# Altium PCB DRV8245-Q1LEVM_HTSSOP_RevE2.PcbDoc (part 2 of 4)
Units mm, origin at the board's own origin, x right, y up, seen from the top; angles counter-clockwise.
Board outline 81.9 x 103.6 mm, 4 copper layers (Top Layer, Signal Layer 1, Signal Layer 2, Bottom Layer), stack 1.554 mm thick; 187 components, 116 nets, 590 pads, 1182 vias.
Unrouted connection lines stored in the file: 116.
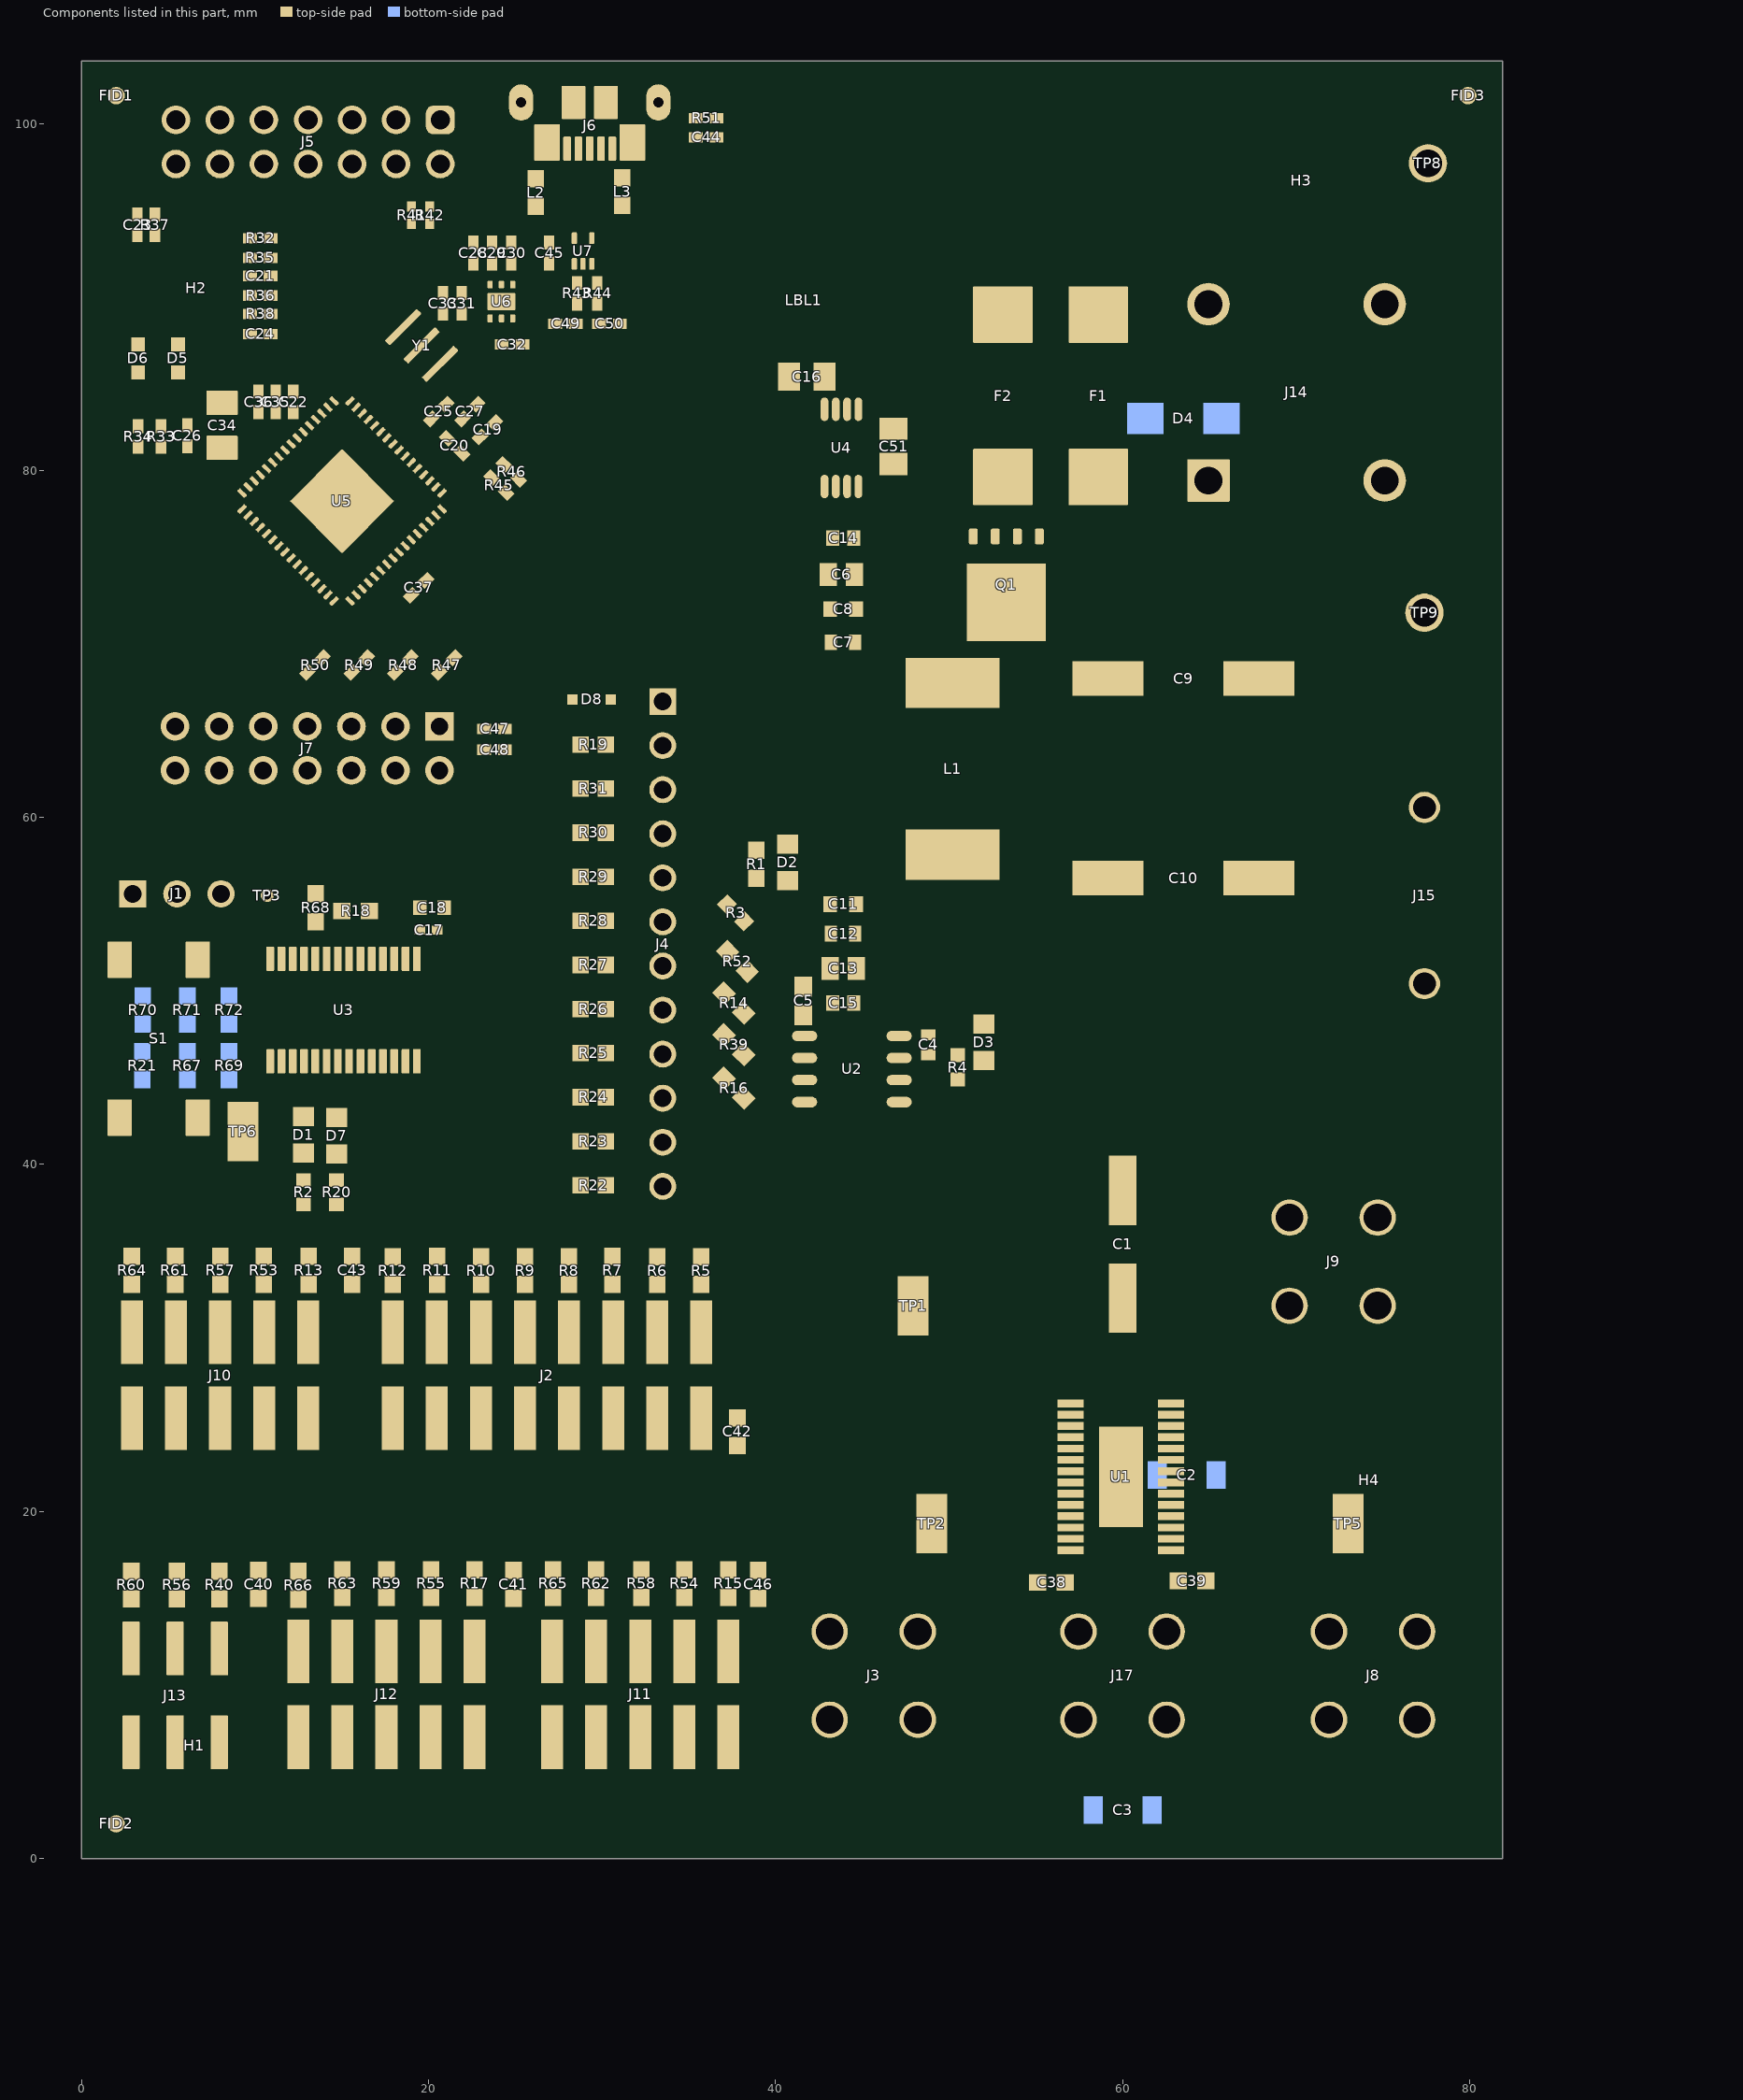
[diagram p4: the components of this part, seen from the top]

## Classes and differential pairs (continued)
component class AssemblyNote: ZZ1 ZZ2 ZZ3 ZZ4
component class Label: LBL1
differential pair USB_D: +USB_D_P -USB_D_N
differential pair EZFET_D: +EZFET_D_P -EZFET_D_N

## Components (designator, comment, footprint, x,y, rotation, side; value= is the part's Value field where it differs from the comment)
C1 "EEE-2AA100UP" SM_RADIAL_E 60,35.4 r270 top value=10uF
C2 "C3216X7R2A104K160AA" 1206_180 63.7,22.1 r180 bottom value=0.1uF
C3 "C3216X7R2A104K160AA" 1206_180 60,2.8 r0 bottom value=0.1uF
C4 "CL10B104JB8NNNC" FP-CL10-0_1-MFG 48.8,46.9 r270 top value=0.1uF
C5 "CL10A226MQ8NUNE" FP-CL10-IPC_A 41.6,49.427 r90 top
C6 "1uF" CAPC2013X135X45LL10T25 43.8,74 r0 top
C7 "0.1uF" CAPC0603(1608)100_L 43.9,70.1 r0 top value=100nF
C8 "CC0603KPX7R9BB103" FP-CC0603-DA-MFG 43.9,72 r0 top value="10 nF"
C9 "EEE-FK1H151P" SM_RADIAL_G 63.5,68 r0 top value=150uF
C10 "EEE-FK1H151P" SM_RADIAL_G 63.5,56.5 r0 top value=150uF
C11 "CC0603KPX7R9BB103" FP-CC0603-DA-MFG 43.9,55 r180 top value="10 nF"
C12 "0.1uF" CAPC0603(1608)100_L 43.9,53.3 r0 top value=100nF
C13 "1uF" CAPC2013X135X45LL10T25 43.9,51.3 r0 top
C14 "1nF" FP-C0603C-CF-MFG#1 44,76.1 r180 top value="1,000 pF"
C15 "1nF" FP-C0603C-CF-MFG#2 43.9,49.3 r180 top value="1,000 pF"
C16 "08055A101JAT2A" 0805_HV 41.8,85.4 r180 top value=100pF
C17 "Capacitor" 0402_065L 20,53.5 r0 top value=4.7uF
C18 "885012206020" 0603L 20.2,54.8 r0 top value=0.1uF
C19 "C1005X5R1A475M050BC" 0402 23.397,82.347 r45 top value=4.7uF
C20 "GRM155R61A104KA01D" 0402 21.501,81.429 r315 top value=0.1uF
C21 "C1005C0G1H330J050BA" 0402 10.302,91.208 r180 top value=33pF
C22 "GRM155R61A104KA01D" 0402 12.2,83.95 r90 top value=0.1uF
C23 "GRM155R71H102KA01D" 0402 3.228,94.149 r270 top value=1000pF
C24 "C1005C0G1H330J050BA" 0402 10.302,87.856 r180 top value=33pF
C25 "GRM155R61A224KE19D" 0402 20.583,83.39 r45 top value=0.22uF
C26 "GRM155R61C474KE01" 0402 6.1,82 r90 top value=0.47uF
C27 "GRM155R61A224KE19D" 0402 22.382,83.39 r45 top value=0.22uF
C28 "885012105012" 0402 22.577,92.525 r90 top value=1uF
C29 "GRM155R61A104KA01D" 0402 23.655,92.525 r90 top value=0.1uF
C30 "GRM155R71C103KA01D" 0402 24.774,92.525 r90 top value=0.01uF
C31 "2.2uF" 0402 21.905,89.625 r90 top
C32 "GRM155R71C103KA01D" 0402 24.814,87.256 r0 top value=0.01uF
C33 "885012105012" 0402 20.831,89.625 r90 top value=1uF
C34 "T520A106M010ATE080" 3216-18 8.1,82.6 r90 top value=10uF
C35 "GRM155R61A104KA01D" 0402 11.19,83.95 r90 top value=0.1uF
C36 "GRM155R61A104KA01D" 0402 10.205,83.95 r90 top value=0.1uF
C37 "GRM155R61A104KA01D" 0402 19.43,73.233 r225 top value=0.1uF
C38 "CGA3E2X7R2A102K080AA" 0603 55.9,15.9 r180 top value=1000pF
C39 "CGA3E2X7R2A102K080AA" 0603 64,16 r0 top value=1000pF
C40 "CGA3E2X7R2A102K080AA" 0603 10.2,15.8 r270 top value=1000pF
C41 "CGA3E2X7R2A102K080AA" 0603 24.9,15.8 r270 top value=1000pF
C42 "CGA3E2X7R2A102K080AA" 0603 37.8,24.6 r90 top value=1000pF
C43 "CGA3E2X7R2A102K080AA" 0603 15.6,33.9 r270 top value=1000pF
C44 "GRM155R61A224KE19D" 0402 36,99.2 r0 top value=0.22uF
C45 "GRM155R61A104KA01D" 0402 26.955,92.525 r90 top value=0.1uF
C46 "CGA3E2X7R2A102K080AA" 0603 39,15.8 r270 top value=1000pF
C47 "GRM1555C1H100FA01D" 0402 23.8,65.1 r180 top value=10pF
C48 "GRM1555C1H100FA01D" 0402 23.8,63.9 r180 top value=10pF
C49 "GRM1555C1H100FA01D" 0402 27.891,88.458 r180 top value=10pF
C50 "GRM1555C1H100FA01D" 0402 30.429,88.458 r0 top value=10pF
C51 "C2012X5R1H225K125AB" 0805_HV 46.8,81.384 r90 top value=2.2uF
D1 "150080VS75000" 0805_A 12.8,41.7 r90 top
D2 "150080SS75000" 0805_A 40.7,57.4 r90 top
D3 "150080VS75000" 0805_A 52,47.05 r90 top
D4 "SMAJ36CA" FP-SMAJ-CA-MFG 63.5,83 r180 bottom
D5 "150060RS75000" WL-SMCW_RED 5.561,86.456 r270 top value=Red
D6 "CMP-0002894-2" WL-SMCW_GREEN 3.258,86.456 r270 top value=Green
D7 "150080VS75000" 0805_A 14.7,41.65 r90 top
D8 "BAT165E6327HTSA1" SOD-323 29.4,66.8 r180 top value=40V
F1 "0463030.ER" Fuse_0463 58.6,84.3 r90 top
F2 "0463030.ER" Fuse_0463 53.1,84.3 r90 top
FID1 "Fiducial" Fiducial10-20 2,101.6 r0 top
FID2 "Fiducial" Fiducial10-20 2,2 r90 top
FID3 "Fiducial" Fiducial10-20 79.9,101.6 r0 top
H1 "SJ-5303 (CLEAR)" Bumpon_SJ5003Transparent 6.5,6.5 r0 bottom
H2 "SJ-5303 (CLEAR)" Bumpon_SJ5003Transparent 6.6,90.5 r0 bottom
H3 "SJ-5303 (CLEAR)" Bumpon_SJ5003Transparent 70.3,96.7 r0 bottom
H4 "SJ-5303 (CLEAR)" Bumpon_SJ5003Transparent 74.2,21.8 r180 bottom
J1 "PR20203VBNN" FP-PR20203VBNN-MFG 5.5,55.6 r0 top
J2 "TSM-108-01-L-DV" Samtec_TSM-108-01-x-DV 26.832,27.851 r270 top
J3 "CT3151SP-2" CTE_CT3151SP-2 45.66,-10.898 r90 top
J4 "PBC12SABN" Sullins_PxC12SABN 33.5,52.71 r270 top
J5 "61301421121" Wurth_61301421121 13.056,98.93 r270 top
J6 "CMP-0055311-1" Molex_1051640001 29.291,102.654 r180 top
J7 "PEC07DAAN" CONN_PEC07DAAN 13.015,63.978 r180 top
J8 "CT3151SP-2" CTE_CT3151SP-2 74.44,-10.898 r90 top
J9 "CT3151SP-2" CTE_CT3151SP-2 93.6,34.4 r180 top
J10 "TSM-105-01-L-DV-P" Samtec_TSM-105-01-x-DV 7.99,27.851 r270 top
J11 "TSM-105-01-L-DV-P" Samtec_TSM-105-01-x-DV 32.204,9.465 r270 top
J12 "TSM-105-01-L-DV-P" Samtec_TSM-105-01-x-DV 17.577,9.465 r270 top
J13 "61000621121" Wurth_61000621121 5.4,9.4 r270 top
J14 "691256610002" FP-691256610002_HDR2-MFG 72.5,84.5 r90 top
J15 "D3082-05" Harwin_D3082-05 77.4,55.5 r90 top
J17 "CT3151SP-0" CTE_CT3151SP-0 60,-10.898 r90 top
L1 "1uH" WE-HCC-1210 50.2,62.8 r270 top
L2 "BLM18AG151BH1D" 0603 26.174,96.01 r270 top value="150 ohm"
L3 "BLM18AG151BH1D" 0603 31.154,96.066 r270 top value="150 ohm"
LBL1 "THT-14-423-10" Label_650x200 41.6,89.8 r0 top
Logo1 "CE Mark" CE_Mark_5mm 33.6,84 r180 bottom
Logo2 "Texas Instruments" TI_Stacked_Overlay_Small 55.2,99 r0 top
Logo3 "FCC disclaimer" FCC_disclaimer -79.62,84.1 r270 bottom
Logo4 "WEEE logo" WEEE_Minimum 33.7,76.8 r180 bottom
Logo5 "CAUTION.  READ USER GUIDE BEFORE USE" IEC_Caution_Small 60.4,47.9 r0 top
LOGO6 "CAUTION HOT SURFACE" IEC_HotSurface_Small 52.2,26.1 r0 top
Q1 "CSD18513Q5A" DQJ0008A 53.3,73.4 r270 top value=40V
R1 "RC0603JR-0710KL" 0603 38.9,57.3 r90 top value=10k
R2 "CMP-0025785-4" 0603L 12.8,38.4 r90 top value=330
R3 "CMP-0025785-4" 0603L 37.7,54.5 r315 top value=330
R4 "CRCW06034K99FKEAC" 0603L 50.5,45.6 r270 top value=4.99k
R5 "RC0603FR-07470RL" 0603 35.722,33.882 r270 top value=470
R6 "RC0603FR-07680RL" 0603 33.182,33.882 r270 top value=680
R7 "RC0603FR-071KL" 0603 30.6,33.9 r270 top value=1.00k
R8 "RC0603FR-071K5L" 0603 28.102,33.882 r270 top value=1.50k
R9 "RC0603FR-072K2L" 0603 25.562,33.882 r270 top value=2.20k
R10 "RC0603FR-073K3L" 0603 23.022,33.882 r270 top value=3.30k
R11 "RC0603FR-074K7L" 0603 20.5,33.9 r270 top value=4.70k
R12 "RC0603FR-076K8L" 0603 17.942,33.882 r270 top value=6.80k
R13 "PMR03EZPJ000" 0603 13.1,33.9 r90 top value=0
R14 "PMR03EZPJ000" 0603 37.6,49.3 r135 top value=0
R15 "PMR03EZPJ000" 0603 37.284,15.846 r90 top value=0
R16 "PMR03EZPJ000" 0603 37.6,44.4 r135 top value=0
R17 "PMR03EZPJ000" 0603 22.657,15.846 r90 top value=0
R18 "RC0603JR-0747KL" 0603 15.8,54.6 r180 top value=47k
R19 "CRCW06030000Z0EAHP" RESC1609X55X30NL10T20 29.5,64.2 r0 top value=0
R20 "CMP-0025785-4" 0603L 14.7,38.4 r90 top value=330
R21 "RC0603JR-0710KL" 0603 3.5,45.7 r90 bottom value=10k
R22 "CRCW06030000Z0EAHP" RESC1609X55X30NL10T20 29.5,38.8 r0 top value=0
R23 "CRCW06030000Z0EAHP" RESC1609X55X30NL10T20 29.5,41.34 r0 top value=0
R24 "CRCW06030000Z0EAHP" RESC1609X55X30NL10T20 29.5,43.88 r0 top value=0
R25 "CRCW06030000Z0EAHP" RESC1609X55X30NL10T20 29.5,46.42 r0 top value=0
R26 "CRCW06030000Z0EAHP" RESC1609X55X30NL10T20 29.5,48.96 r0 top value=0
R27 "CRCW06030000Z0EAHP" RESC1609X55X30NL10T20 29.5,51.5 r0 top value=0
R28 "CRCW06030000Z0EAHP" RESC1609X55X30NL10T20 29.5,54.04 r0 top value=0
R29 "CRCW06030000Z0EAHP" RESC1609X55X30NL10T20 29.5,56.58 r0 top value=0
R30 "CRCW06030000Z0EAHP" RESC1609X55X30NL10T20 29.5,59.12 r0 top value=0
R31 "CRCW06030000Z0EAHP" RESC1609X55X30NL10T20 29.5,61.66 r0 top value=0
R32 "CRCW0402240KFKED" 0402 10.314,93.383 r180 top value=240k
R33 "CRCW0402470RJNED" 0402 4.578,81.956 r270 top value=470
R34 "CRCW0402390RJNED" 0402 3.258,81.956 r270 top value=390
R35 "CRCW0402150KFKED" 0402 10.302,92.252 r0 top value=150k
R36 "RC0402FR-07220KL" 0402 10.305,90.081 r180 top value=220k
R37 "CRCW040247K0JNED" 0402 4.228,94.149 r270 top value=47k
R38 "RC0402FR-07220KL" 0402 10.305,89.02 r0 top value=220k
R39 "PMR03EZPJ000" 0603 37.6,46.9 r135 top value=0
R40 "PMR03EZPJ000" 0603 7.95,15.761 r90 top value=0
R41 "ERJ-2GE0R00X" 0402L 19.011,94.708 r90 top value=0
R42 "ERJ-2GE0R00X" 0402L 20.062,94.708 r90 top value=0
R43 "CRCW040227R0JNED" 0402 28.559,90.208 r270 top value=27
R44 "CRCW040227R0JNED" 0402 29.728,90.208 r270 top value=27
R45 "CRCW04021K40FKED" 0402 24.051,79.155 r315 top value=1.40k
R46 "CRCW04021M00JNED" 0402 24.774,79.918 r135 top value=1.0Meg
R47 "CRCW040210R0FKED" 0402 21.043,68.782 r225 top value=10.0
R48 "CRCW040210R0FKED" 0402 18.519,68.782 r225 top value=10.0
R49 "CRCW040210R0FKED" 0402 16.003,68.783 r225 top value=10.0
R50 "CRCW040210R0FKED" 0402 13.455,68.782 r225 top value=10.0
R51 "CRCW040233K0JNED" 0402 36,100.3 r180 top value=33k
R52 "PMR03EZPJ000" 0603 37.8,51.7 r135 top value=0
R53 "CRCW06038K20JNEA" 0603 10.5,33.9 r270 top value=8.2k
R54 "CRCW06038K20JNEA" 0603 34.744,15.846 r270 top value=8.2k
R55 "CRCW06038K20JNEA" 0603 20.147,15.846 r270 top value=8.2k
R56 "CRCW06038K20JNEA" 0603 5.501,15.761 r270 top value=8.2k
R57 "CRCW060322K0JNEA" 0603 8,33.9 r270 top value=22k
R58 "CRCW060322K0JNEA" 0603 32.265,15.846 r270 top value=22k
R59 "CRCW060322K0JNEA" 0603 17.577,15.846 r270 top value=22k
R60 "CRCW060382K0JNEA" 0603 2.87,15.761 r90 top value=82k
R61 "CRCW060347K0FKEA" 0603 5.4,33.9 r270 top value=47.0k
R62 "CRCW060347K0FKEA" 0603 29.664,15.846 r270 top value=47.0k
R63 "CRCW060347K0FKEA" 0603 15.037,15.846 r270 top value=47.0k
R64 "CRCW0603100KDHEAP" 0603 2.9,33.9 r270 top value=100k
R65 "CRCW0603100KDHEAP" 0603 27.176,15.846 r270 top value=100k
R66 "CRCW0603100KDHEAP" 0603 12.497,15.751 r270 top value=100k
R67 "RC0603JR-0710KL" 0603 6.1,45.7 r90 bottom value=10k
R68 "RC0603JR-0710KL" 0603 13.5,54.8 r270 top value=10k
R69 "RC0603JR-0710KL" 0603 8.5,45.7 r90 bottom value=10k
R70 "RC0603JR-0710KL" 0603 3.521,48.9 r90 bottom value=10k
R71 "RC0603JR-0710KL" 0603 6.1,48.9 r90 bottom value=10k
R72 "RC0603JR-0710KL" 0603 8.5,48.9 r90 bottom value=10k
S1 "FSM4JSMA" SW_FSM4JSMA 4.45,47.25 r0 top
TP1 "5015" Testpoint_Keystone_Miniature 47.93,31.85 r270 top
TP2 "5015" Testpoint_Keystone_Miniature 49,19.3 r270 top
TP3 "TP_H0.45P0.75" TP_H045P075 10.7,55.5 r90 top
TP5 "5015" Testpoint_Keystone_Miniature 73,19.3 r90 top
TP6 "5015" Testpoint_Keystone_Miniature 9.3,41.9 r90 top
TP8 "5010" Keystone5010 77.6,97.7 r180 top
TP9 "5011" Keystone5011 77.4,71.8 r0 top
U1 "DRV8245S-Q1" HTSSOP-28-epod 57,26.225 r0 top
U2 "LM9036M-3.3/NOPB" D0008A_N 44.4,45.5 r0 top
U3 "MSP430G2553IPW28R" PW0028A_N 15.1,48.9 r270 top
U4 "LM74610QDGKRQ1" DGK0008A_N 43.8,81.3 r270 top
U5 "CMP-0039269-4" RGC0064B 15.016,78.233 r315 top
U6 "TPS73533DRVR" DRV0006A 24.201,89.734 r90 top
U7 "TPD2E001DRLR" DRL0005A 28.903,92.643 r90 top
Y1 "CSTNR4M00GH5L000R0" MuRata_CSTNR 19.6,87.2 r135 top
ZZ1 "This Assembly Note is for PCB labels only" AssemblyNoteLabel 4.411,120.725 r0 top
ZZ2 "These assemblies are ESD sensitive, ESD precautions shall be observed." AssemblyNote 4.411,117.959 r0 top
ZZ3 "These assemblies must be clean and free from flux and all contaminants. Use of no clean flux is not acceptable." AssemblyNote 4.411,115.71 r0 top
ZZ4 "These assemblies must comply with workmanship standards IPC-A-610 Class 2, unless otherwise specified." AssemblyNote 4.411,113.461 r0 top

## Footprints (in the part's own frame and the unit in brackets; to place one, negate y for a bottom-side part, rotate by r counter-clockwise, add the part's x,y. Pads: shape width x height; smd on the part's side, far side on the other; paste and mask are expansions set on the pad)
0402 [mm] "0402 from SM-752 data"
  rect 0.8x0.6 smd: 1(-0.6,0) 2(0.6,0)
  silkscreen extent -1.22,-0.52 1.22,0.52, body extent -0.55,-0.3 0.55,0.3, height 0.6
0402_065L [mm] "0402"
  rect 0.6x0.5 smd: 1(-0.5,0) 2(0.5,0)
  body extent -0.55,-0.3 0.55,0.3, height 0.65
0402L [mm] "0402 from SM-752 data"
  rect 0.6x0.5 smd: 1(-0.5,0) 2(0.5,0)
  body extent -0.55,-0.3 0.55,0.3, height 0.6
0603 [mm] "0603 from SM-752 data"
  rect 1x0.95 smd: 1(-0.8,0) 2(0.8,0)
  silkscreen extent -1.52,-0.69 1.52,0.69, body extent -0.87,-0.47 0.87,0.47, height 1
0603L [mm] "0603 from SM-752 data"
  rect 0.8x0.85 smd: 1(-0.7,0) 2(0.7,0)
  silkscreen extent -0.07,-0.33 0.07,0.33, body extent -0.87,-0.47 0.87,0.47, height 1
0805_A [mm] "Chip LED, 2-Leads, Body 2.0x1.3mm, IPC Medium Density"
  rect 1.1x1.2 smd: 1(-1.05,0) 2(1.05,0)
  silkscreen extent -0.15,-0.5 0.15,0.5, body extent -1,-0.62 1,0.63, height 0.68
0805_HV [mil] "0805 with 30mil clearance between pads"
  rect 50x63 smd: 1(-40,0) 2(40,0)
  silkscreen extent -74,-40 74,40, body extent -43,-29 43,29, height 57
1206_180 [mm] "1206_180"
  rect 1.1x1.6 smd: 1(-1.7,0) 2(1.7,0)
  silkscreen extent -0.9,-1 0.9,1, body extent -1.75,-0.95 1.75,0.95, height 1.8
3216-18 [mm] "Based on AVX recommendation in http://www.avx.com/download/software/literature/AVX-Footprint-Library.pdf"
  rrect7% 1.4x1.8 smd: 1(-1.3,0) 2(1.3,0)
  silkscreen extent -1.9,-1.13 0.8,1.12, body extent -1.7,-0.9 1.7,0.9, height 1.82
AssemblyNote [mm] "Assembly Note"
AssemblyNoteLabel [mm] "Assembly Note for PCB Labels"
Bumpon_SJ5003Transparent [mil] "3M Hemispherical Bumpon transparent"
  round 1 on Mech4: 0(0,0)
  silkscreen extent -228,-228 228,228, body extent -219,-219 219,219, height 197
CAPC0603(1608)100_L [mm] "Chip Capacitor, Body 1.6x0.8mm, Height 1.0mm, IPC High Density"
  rect 0.7x0.9 smd: 1(-0.7,0) 2(0.7,0)
  silkscreen extent -0.05,-0.35 0.05,0.35, body extent -0.87,-0.47 0.88,0.48, height 1
CAPC2013X135X45LL10T25 [mm] "Chip Capacitor, 2-Leads, Body 2.00x1.25mm, IPC High Density"
  rect 1x1.3 smd: 1(-0.75,0) 2(0.75,0)
  body extent -1.05,-0.67 1.05,0.68, height 1.35
CE_Mark_5mm [mm] "Minimum text height for CE Mark"
  silkscreen extent -3.5,-2.5 3.5,2.5
CONN_PEC07DAAN [mm] "SULLINS"
  rect 1.65x1.65 hole 1.016 mask+0: 1(-7.62,-1.27)
  round 1.65 hole 1.016 mask+0: 2(-7.62,1.27) 3(-5.08,-1.27) 4(-5.08,1.27) 5(-2.54,-1.27) 6(-2.54,1.27) 7(0,-1.27) 8(0,1.27) 9(2.54,-1.27) 10(2.54,1.27) 11(5.08,-1.27) 12(5.08,1.27) 13(7.62,-1.27) 14(7.62,1.27)
  silkscreen extent -9.99,-2.6 8.89,2.54, body extent -8.95,-2.6 8.95,2.6, height 8.38
CTE_CT3151SP-0 [mm] "Banana Jack Insul Nylon Black, R/A, TH"
  round 2.1 hole 1.6: 1(18.898,-2.54) 1(18.898,2.54) 1(23.978,-2.54) 1(23.978,2.54)
  silkscreen extent 0.44,-6.75 18.02,6.75, body extent -3.06,-6.7 24.64,6.8, height 14.37
CTE_CT3151SP-2 [mm] "Banana Jack Insul Nylon Red, R/A, TH"
  round 2.1 hole 1.6: 1(18.898,-2.54) 1(18.898,2.54) 1(23.978,-2.54) 1(23.978,2.54)
  silkscreen extent 0.44,-6.75 18.02,6.75, body extent -3.06,-6.75 24.64,6.75, height 14.37
D0008A_N [mm] "SOIC, 8-Leads, Body 4.9x3.9mm, Pitch 1.27mm, IPC Medium Density"
  oval 1.45x0.6 smd: 1(-2.725,1.905) 2(-2.725,0.635) 3(-2.725,-0.635) 4(-2.725,-1.905) 5(2.725,-1.905) 6(2.725,-0.635) 7(2.725,0.635) 8(2.725,1.905)
  silkscreen extent -3.3,-2.5 0.9,2.5, body extent -3,-2.45 3,2.45, height 1.63
DGK0008A_N [mm] "TSOP, 8-Leads, Body 3x3mm, Pitch 0.65mm, IPC Medium Density"
  oval 1.35x0.45 smd: 1(-2.225,0.975) 2(-2.225,0.325) 3(-2.225,-0.325) 4(-2.225,-0.975) 5(2.225,-0.975) 6(2.225,-0.325) 7(2.225,0.325) 8(2.225,0.975)
  silkscreen extent -2.75,-1.55 0.95,1.55, body extent -2.45,-1.5 2.45,1.5, height 0.96
DQJ0008A [mm] "SMD, 8-Leads, Body 5.75x4.9mm"
  rrect39% 0.91x0.51 smd paste-0.05 mask-0.05: 1(-2.795,1.905) 2(-2.795,0.635) 3(-2.795,-0.635) 4(-2.795,-1.905) 5(2.795,-1.905) 6(2.795,-0.635) 7(2.795,0.635) 8(2.795,1.905)
  rrect8% 1.58x1.25 on Top Paste: 9(-0.38,1.45) 9(-0.38,0) 9(-0.38,-1.45) 9(1.4,1.45) 9(1.4,0) 9(1.4,-1.45)
  rrect3% 3.48x4.47 on Top Solder: 9(0.55,0)
  rrect2% 4.49x4.57 smd paste-2.5 mask-2.5: 9(1.005,0)
  silkscreen extent -3,-2.6 3,2.6, body extent -3.13,-2.45 3.13,2.45, height 1.15
DRL0005A [mm] "SOTFL, 5-Flat Leads, Body 1.2x1.6x0.6mm, Pitch 0.5mm, TI recommended"
  rrect33% 0.67x0.3 smd: 1(-0.74,0.5) 2(-0.74,0) 3(-0.74,-0.5) 4(0.74,-0.5) 5(0.74,0.5)
  silkscreen extent -0.9,-0.95 0.5,0.95, body extent -0.85,-0.85 0.85,0.85, height 0.62
DRV0006A [mm] "SON, 6-Leads, Body 2x2mm, Pitch 0.65mm, Thermal Pad 1.6x1mm, TI Recommended"
  rrect33% 0.45x0.3 smd: 1(-0.975,0.65) 2(-0.975,0) 3(-0.975,-0.65) 4(0.975,-0.65) 5(0.975,0) 6(0.975,0.65)
  rrect14% 1x0.7 on Top Paste: 7(0,0.45) 7(0,-0.45)
  rrect10% 1x1.6 smd paste-0.5: 7(0,0)
  silkscreen extent -1.05,-1.2 1.05,1.2, body extent -1.05,-1.05 1.05,1.05, height 0.81
FCC_disclaimer [mm]
Fiducial10-20 [mm]
  round 1 smd mask+0.5: 1(0,0)
  Top Layer keep-out circle w1.178: c0,0 r0.5
FP-691256610002_HDR2-MFG [mm]
  rrect4% 2.45x2.45 hole 1.6 paste-1000 mask+0: 1(-5.08,7.55)
  round 2.45 hole 1.6 paste-1000 mask+0: 1(-5.08,-2.61) 2(5.08,7.55) 2(5.08,-2.61)
  silkscreen extent -11,-9.2 10.21,9.2, body extent -10.31,-9.3 10.31,9.3, height 0.25
FP-C0603C-CF-MFG#1 [mm]
  rect 0.75x0.9 smd paste+0 mask+0: 1(-0.5,0) 2(0.7,0)
  silkscreen extent -0.78,-0.85 0.98,0.85, body extent -1.1,-0.6 1.3,0.6, height 0.25
FP-C0603C-CF-MFG#2 [mm]
  rect 0.75x0.9 smd paste+0 mask+0: 1(-0.6,0) 2(0.6,0)
  silkscreen extent -0.87,-0.85 0.88,0.85, body extent -1.2,-0.6 1.2,0.6, height 0.25
FP-CC0603-DA-MFG [mm]
  rect 0.8x0.9 smd paste+0 mask+0: 1(-0.75,0) 2(0.75,0)
  silkscreen extent -0.85,-0.85 0.85,0.85, body extent -1.35,-0.75 1.35,0.75, height 0.25
FP-CL10-0_1-MFG [mm]
  rect 0.625x0.825 smd paste+0 mask+0: 1(-0.575,0) 2(0.575,0)
  silkscreen extent -0.8,-0.79 0.8,0.79, body extent -0.99,-0.55 0.99,0.55, height 0.25
FP-CL10-IPC_A [mm]
  rect 1.158x1.012 smd paste+0 mask+0: 1(-0.827,0) 2(0.827,0)
  silkscreen extent -1.41,-0.91 1.41,0.91, body extent -1.91,-1.01 1.91,1.01, height 0.25
FP-PR20203VBNN-MFG [mm]
  rect 1.57x1.57 hole 1.02 paste-1000 mask+0: 1(-2.54,0)
  round 1.57 hole 1.02 paste-1000 mask+0: 2(0,0) 3(2.54,0)
  silkscreen extent -4.7,-1.25 3.81,1.25, body extent -3.91,-1.35 3.91,1.35, height 0.25
FP-SMAJ-CA-MFG [mm]
  rect 2.1x1.8 smd paste+0 mask+0: 1(-2.2,0) 2(2.2,0)
  silkscreen extent -2.3,-1.4 2.3,1.39, body extent -2.55,-1.34 2.55,1.33, height 2.29
Fuse_0463 [mm] "SMD, 2-Leads, Body 10.1x3.12mm"
  rrect3% 3.25x3.43 smd: 1(-4.675,0) 2(4.675,0)
  silkscreen extent -2.6,-1.5 2.6,1.5, body extent -5.05,-1.56 5.05,1.56, height 3.12
Harwin_D3082-05 [mm] "Shorting Plug, 10.16mm spacing, TH"
  round 1.8 hole 1.3: 1(-5.08,0) 2(5.08,0)
  silkscreen extent -3.9,-0.53 3.9,0.53, body extent -5.6,-0.52 5.61,0.52, height 6.63
HTSSOP-28-epod [mm]
  rect 1.5x0.45 smd: 1(0,0) 2(0,-0.65) 3(0,-1.3) 4(0,-1.95) 5(0,-2.6) 6(0,-3.25) 7(0,-3.9) 8(0,-4.55) 9(0,-5.2) 10(0,-5.85) 11(0,-6.5) 12(0,-7.15) 13(0,-7.8) 14(0,-8.45) 15(5.8,-8.45) 16(5.8,-7.8) 17(5.8,-7.15) 18(5.8,-6.5) 19(5.8,-5.85) 20(5.8,-5.2) 21(5.8,-4.55) 22(5.8,-3.9) 23(5.8,-3.25) 24(5.8,-2.6) 25(5.8,-1.95) 26(5.8,-1.3) 27(5.8,-0.65) 28(5.8,0)
  rect 2.53x5.8 smd: 29(2.9,-4.225)
  silkscreen extent 1.58,-8.78 4.22,0.33
IEC_Caution_Small [mm]
  silkscreen extent -2.72,-2.36 2.72,2.35
IEC_HotSurface_Small [mm]
  silkscreen extent -2.72,-2.36 2.72,2.35
Keystone5010 [mil] "Keystone Multipurpose loops"
  round 87 hole 63: 1(0,0)
  silkscreen extent -70,-70 70,70, body extent -63,-63 63,62, height 319
Keystone5011 [mil] "Keystone Multipurpose loops"
  round 87 hole 63: 1(0,0)
  silkscreen extent -70,-70 70,70, body extent -63,-63 63,62, height 319
Label_650x200 [mil] "Thermal Transfer Label"
  round 1 on Mech13: 0(0,0)
  silkscreen extent -325,-100 325,100, body extent -325,-100 325,100, height 1
Molex_1051640001 [mm] "Receptacle, USB 2.0, Micro B, 5 Pos, 0.65mm Pitch, R/A, SMT"
  rrect22% 0.45x1.38 smd: 1(1.3,4.11) 2(0.65,4.11) 3(0,4.11) 4(-0.65,4.11) 5(-1.3,4.11)
  rrect7% 1.475x2.1 smd: 6(-2.462,3.75) 11(2.462,3.75)
  rrect100% 1.4x2.1 hole 0.6 slot 1.3 at 90 deg: 7(-3.95,1.45) 10(3.95,1.45)
  rrect7% 1.375x1.9 smd: 8(-0.938,1.45) 9(0.938,1.45)
  silkscreen extent 1.2,5.1 1.4,5.4, body extent -4.1,-0.7 4.1,4.47, height 2.45
MuRata_CSTNR [mm] "SMD, 3-Leads, Body 4.5x2mm, Pitch 1.5mm"
  rrect25% 0.4x2.6 smd: 1(-1.5,0) 2(0,0) 3(1.5,0)
  body extent -2.3,-1.05 2.3,1.05, height 1.2
PW0028A_N [mm] "SOP, 28-Leads, Body 9.8x4.5mm, Pitch 0.65mm, IPC Medium Density"
  rrect22% 1.4x0.45 smd: 1(-2.95,4.225) 2(-2.95,3.575) 3(-2.95,2.925) 4(-2.95,2.275) 5(-2.95,1.625) 6(-2.95,0.975) 7(-2.95,0.325) 8(-2.95,-0.325) 9(-2.95,-0.975) 10(-2.95,-1.625) 11(-2.95,-2.275) 12(-2.95,-2.925) 13(-2.95,-3.575) 14(-2.95,-4.225) 15(2.95,-4.225) 16(2.95,-3.575) 17(2.95,-2.925) 18(2.95,-2.275) 19(2.95,-1.625) 20(2.95,-0.975) 21(2.95,-0.325) 22(2.95,0.325) 23(2.95,0.975) 24(2.95,1.625) 25(2.95,2.275) 26(2.95,2.925) 27(2.95,3.575) 28(2.95,4.225)
  silkscreen extent -3.07,-4.9 1.85,5.13, body extent -3.21,-4.85 3.21,4.85, height 1
RESC1609X55X30NL10T20 [mm] "Chip Resistor, 2-Leads, Body 1.60x0.85mm, IPC Medium Density"
  rect 0.95x0.95 smd: 1(-0.725,0) 2(0.725,0)
  body extent -0.85,-0.48 0.85,0.48, height 0.55
RGC0064B [mm] "VQFN-64"
  rrect42% 0.6x0.24 smd mask+0.07: 1(-4.4,3.75) 2(-4.4,3.25) 3(-4.4,2.75) 4(-4.4,2.25) 5(-4.4,1.75) 6(-4.4,1.25) 7(-4.4,0.75) 8(-4.4,0.25) 9(-4.4,-0.25) 10(-4.4,-0.75) 11(-4.4,-1.25) 12(-4.4,-1.75) 13(-4.4,-2.25) 14(-4.4,-2.75) 15(-4.4,-3.25) 16(-4.4,-3.75) 33(4.4,-3.75) 34(4.4,-3.25) 35(4.4,-2.75) 36(4.4,-2.25) 37(4.4,-1.75) 38(4.4,-1.25) 39(4.4,-0.75) 40(4.4,-0.25) 41(4.4,0.25) 42(4.4,0.75) 43(4.4,1.25) 44(4.4,1.75) 45(4.4,2.25) 46(4.4,2.75) 47(4.4,3.25) 48(4.4,3.75)
  rrect42% 0.24x0.6 smd mask+0.07: 17(-3.75,-4.4) 18(-3.25,-4.4) 19(-2.75,-4.4) 20(-2.25,-4.4) 21(-1.75,-4.4) 22(-1.25,-4.4) 23(-0.75,-4.4) 24(-0.25,-4.4) 25(0.25,-4.4) 26(0.75,-4.4) 27(1.25,-4.4) 28(1.75,-4.4) 29(2.25,-4.4) 30(2.75,-4.4) 31(3.25,-4.4) 32(3.75,-4.4) 49(3.75,4.4) 50(3.25,4.4) 51(2.75,4.4) 52(2.25,4.4) 53(1.75,4.4) 54(1.25,4.4) 55(0.75,4.4) 56(0.25,4.4) 57(-0.25,4.4) 58(-0.75,4.4) 59(-1.25,4.4) 60(-1.75,4.4) 61(-2.25,4.4) 62(-2.75,4.4) 63(-3.25,4.4) 64(-3.75,4.4)
  rrect2% 4.25x4.25 smd paste-2.112: 65(0,0)
  body extent -4.5,-4.5 4.5,4.5, height 1
Samtec_TSM-105-01-x-DV [mm] "Header, 2.54mm, 5x2, SMT"
  rect 3.68x1.27 smd: 1(-2.475,5.08) 2(2.475,5.08) 3(-2.475,2.54) 4(2.475,2.54) 5(-2.475,0) 6(2.475,0) 7(-2.475,-2.54) 8(2.475,-2.54) 9(-2.475,-5.08) 10(2.475,-5.08)
  silkscreen extent -1.65,-6.35 1.65,6.49, body extent -3.85,-6.35 3.85,6.35, height 9.65
Samtec_TSM-108-01-x-DV [mm] "Header, 2.54mm, 8x2, SMT"
  rect 3.68x1.27 smd: 1(-2.475,8.89) 2(2.475,8.89) 3(-2.475,6.35) 4(2.475,6.35) 5(-2.475,3.81) 6(2.475,3.81) 7(-2.475,1.27) 8(2.475,1.27) 9(-2.475,-1.27) 10(2.475,-1.27) 11(-2.475,-3.81) 12(2.475,-3.81) 13(-2.475,-6.35) 14(2.475,-6.35) 15(-2.475,-8.89) 16(2.475,-8.89)
  silkscreen extent -1.65,-10.16 1.65,10.3, body extent -3.85,-10.16 3.85,10.16, height 9.65
SM_RADIAL_E [mm] "8 x 6.2mm:  Panasonic E"
  rect 4x1.6 smd: 1(-3.1,0) 2(3.1,0)
  silkscreen extent -4.25,-4.25 4.25,4.25, body extent -4.25,-4.25 4.25,4.25, height 6.5
SM_RADIAL_G [mm] "10 x 10.2mm:  Panasonic G"
  rect 4.1x2 smd: 1(-4.35,0) 2(4.35,0)
  silkscreen extent -5.35,-5.35 5.35,5.35, body extent -5.25,-5.25 5.25,5.25, height 10.5
SOD-323 [mm] "NXP recommended land pattern"
  rect 0.6x0.6 smd paste-0.05: 1(-1.1,0) 2(1.1,0)
  silkscreen extent -2.06,-0.86 1.53,0.86, body extent -1.3,-0.67 1.3,0.68, height 1.1
Sullins_PxC12SABN [mm] "Header, 2.54 mm, 12x1, TH"
  rect 1.55x1.55 hole 1.016: 1(-13.97,0)
  round 1.55 hole 1.016: 2(-11.43,0) 3(-8.89,0) 4(-6.35,0) 5(-3.81,0) 6(-1.27,0) 7(1.27,0) 8(3.81,0) 9(6.35,0) 10(8.89,0) 11(11.43,0) 12(13.97,0)
  silkscreen extent -15.49,-1.75 15.49,1.33, body extent -15.49,-1.33 15.49,1.33, height 8.71
SW_FSM4JSMA [mm] "Alcoswitch"
  rrect7% 1.4x2.1 smd: 1(2.25,4.55) 2(2.25,-4.55) 3(-2.25,4.55) 4(-2.25,-4.55)
  body extent -3,-5 3,5, height 5.09
Testpoint_Keystone_Miniature [mil] "Miniature SMT test point"
  rect 135x70 smd: 1(0,0)
  silkscreen extent -78,-46 78,45, body extent -52,-20 52,20, height 61
TI_Stacked_Overlay_Small [mm]
  silkscreen extent -10.63,-2.49 10.63,2.49
TP_H045P075 [mm] "TP_H0.45P0.75"
  round 0.75 hole 0.45: 1(0,0)
WE-HCC-1210 [mm] "Inductor, 2-Leads, Body 12.1 x 11.4 mm"
  rect 2.9x5.4 smd: 1(-4.95,0) 2(4.95,0)
  silkscreen extent -6.2,-5.85 6.2,5.85, body extent -6.05,-5.68 6.05,5.72, height 9.5
WEEE_Minimum [mm] "WEEElie bin"
  silkscreen extent -2.42,-4.38 2.52,2.65
WL-SMCW_GREEN [mm] "WURTH"
  rect 0.8x0.8 smd: 1(-0.8,0) 2(0.8,0)
  silkscreen extent -1.9,-0.8 1.2,0.8, body extent -0.85,-0.45 0.85,0.45, height 0.8
WL-SMCW_RED [mm] "WURTH"
  rect 0.8x0.8 smd: 1(-0.8,0) 2(0.8,0)
  silkscreen extent -1.9,-0.8 1.2,0.8, body extent -0.85,-0.45 0.85,0.45, height 0.8
Wurth_61000621121 [mm] "Header, 2.54mm, 3x2, SMT"
  rrect10% 3.1x1 smd: 1(-2.7,2.54) 2(2.7,2.54) 3(-2.7,0) 4(2.7,0) 5(-2.7,-2.54) 6(2.7,-2.54)
  body extent -3.75,-3.81 3.75,3.81, height 9.6
Wurth_61301421121 [mm] "Header, 2.54mm, 7x2, TH"
  rrect50% 1.65x1.65 hole 1.1: 1(-1.27,7.62)
  round 1.65 hole 1.1: 2(1.27,7.62) 3(-1.27,5.08) 4(1.27,5.08) 5(-1.27,2.54) 6(1.27,2.54) 7(-1.27,0) 8(1.27,0) 9(-1.27,-2.54) 10(1.27,-2.54) 11(-1.27,-5.08) 12(1.27,-5.08) 13(-1.27,-7.62) 14(1.27,-7.62)
  body extent -2.54,-8.89 2.54,8.89, height 8.55

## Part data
C1: library part CMP-0011164-2, "CAP, AL, 10 uF, 100 V, +/- 20%, AEC-Q200 Grade 3, SMD", Cap_Case=8.0x6.0mm, Manufacturer=Panasonic, Supplier Part Number 1=PCE3966CT-ND, Tolerance_%=20%, Value1=Unknown, Value2=100V, ValueDisplayed=10uF
C2 C3: library part CMP-0008709-1, "CAP, CERM, 0.1 uF, 100 V, +/- 10%, X7R, 1206", Cap_Case=1206_180, Manufacturer=TDK, Supplier Part Number 1=445-1377-1-ND, TempCo=X7R, Tolerance_%=10%, Value1="0.030343 ohm", Value2=100V, ValueDisplayed=0.1uF
C4: library part CMP-13271-000011-1, "CAP CER 0.1UF 50V X7R 0603", Capacitance=100nF, Manufacturer="Samsung Electro-Mechanics America, Inc", Package=CL10-0.1, Temperature="-55°C to +125°C", Temperature Characteristic=X7R, Temperature Coefficient=15%, Temperature Range High=+125°C, Temperature Range Low=-55°C, Tolerance=5%, Voltage Rating=50V
C5: library part CMP-13271-003053-1, "Cap Ceramic 22uF 6.3V X5R ±20% Pad SMD 0603 +85°C T/R", Capacitance=22uF, Case/Package=0603, Case Code (Metric)=1608, Max Operating Temperature=85°C, Min Operating Temperature=-55°C, Tolerance=20%, Voltage Rating=6.3V
C6 C13: library part CMP-2007-03579-1, "GRM21BR71H105KA12L", Manufacturer=Murata
C7 C12: library part CMP-1035-02591-1, "CAP 100nF 50V ±5% 0603 (1608 Metric) Thickness 1mm SMD", Case-EIA=0603, Case-Metric=1608, Rated Voltage="50 V", Tolerance=±5%
C8 C11: library part CMP-1035-02321-3, "CAP CER 10000PF 50V X7R 0603", Capacitance="10 nF", Manufacturer=YAGEO, Package=CC0603-DA, Temperature="-55°C to +125°C", Temperature Characteristic=X7R, Temperature Coefficient=15%, Temperature Range High=+125°C, Temperature Range Low=-55°C, Tolerance=0.1, Voltage="50 V"
C9 C10: library part CMP-0011178-2, "CAP, AL, 150 uF, 50 V, +/- 20%, 0.18 ohm, AEC-Q200 Grade 2, SMD", Cap_Case=G, Manufacturer=Panasonic, Supplier Part Number 1=PCE3810CT-ND, Tolerance_%=20%, Value1="0.18 ohm", Value2=50V, ValueDisplayed=150uF
C14 C15: library part CMP-03020-030804-1, "CAP CER 1000PF 50V X7R 0603", Capacitance="1,000 pF", Manufacturer=KEMET, Manufacturer Part Number=C0603C102J5RACAUTO, Package=C0603C-CF, Temperature="-55°C to +125°C", Temperature Characteristic=X7R, Temperature Coefficient=30ppm/°C, Temperature Range High=+125°C, Temperature Range Low=-55°C, Tolerance=0.05, Voltage Rating="50 V"
C16: library part CMP-0007580-1, "CAP, CERM, 100 pF, 50 V, +/- 5%, C0G/NP0, 0805", Cap_Case=0805, Manufacturer=AVX, Supplier Part Number 1=478-1316-1-ND, TempCo=C0G/NP0, Tolerance_%=5%, Value1="0.356 ohm", Value2=50V, ValueDisplayed=100pF
C17: library part CMP-0006268-2, "CAP, CERM, 4.7 uF, 10 V, +/- 10%, X5R, 0402", Cap_Case=0402_065, Manufacturer=TDK, PartNumber=C1005X5R1A475K050BC, Supplier Part Number 1=445-13820-1-ND, TempCo=X5R, Tolerance_%=10%, Value1="0.003417 ohm", Value2=10V, ValueDisplayed=4.7uF
C18: library part CMP-0064931-4, "CAP, CERM, 0.1 uF, 10 V,+/- 10%, X7R, 0603", Cap_Case=0603, Manufacturer="Wurth Elektronik", Supplier Part Number 1=732-7939-1-ND, TempCo=X7R, Tolerance_%=10%, Value1=Unknown, Value2=10V, ValueDisplayed=0.1uF
C19: library part CMP-0006269-2, "CAP, CERM, 4.7 uF, 10 V, +/- 20%, X5R, 0402", Cap_Case=0402, Manufacturer=TDK, Supplier Part Number 1=445-8023-1-ND, TempCo=X5R, Tolerance_%=20%, Value1=Unknown, Value2=10V, ValueDisplayed=4.7uF
C20 C22 C29 C35 C36 C37 C45: library part CMP-0006562-2, "CAP, CERM, 0.1 uF, 10 V, +/- 10%, X5R, 0402", Cap_Case=0402, Manufacturer=MuRata, Supplier Part Number 1=490-1318-1-ND, TempCo=X5R, Tolerance_%=10%, Value1=Unknown, Value2=10V, ValueDisplayed=0.1uF
C21 C24: library part CMP-0006250-2, "CAP, CERM, 33 pF, 50 V, +/- 5%, C0G/NP0, 0402", Cap_Case=0402, Manufacturer=TDK, Supplier Part Number 1=445-1241-1-ND, TempCo=C0G/NP0, Tolerance_%=5%, Value1=Unknown, Value2=50V, ValueDisplayed=33pF
C23: library part CMP-0006673-2, "CAP, CERM, 1000 pF, 50 V, +/- 10%, X7R, 0402", Cap_Case=0402, Manufacturer=MuRata, Supplier Part Number 1=490-1303-1-ND, TempCo=X7R, Tolerance_%=10%, Value1=Unknown, Value2=50V, ValueDisplayed=1000pF
C25 C27 C44: library part CMP-0006570-2, "CAP, CERM, 0.22 uF, 10 V, +/- 10%, X5R, 0402", Cap_Case=0402, Manufacturer=MuRata, Supplier Part Number 1=490-3910-1-ND, TempCo=X5R, Tolerance_%=10%, Value1=Unknown, Value2=10V, ValueDisplayed=0.22uF
C26: library part CMP-0006600-2, "CAP, CERM, 0.47 uF, 16 V, +/- 10%, X5R, 0402", Cap_Case=0402, Manufacturer=MuRata, TempCo=X5R, Tolerance_%=10%, Value1=Unknown, Value2=16V, ValueDisplayed=0.47uF
C28 C33: library part CMP-0064924-2, "CAP, CERM, 1 uF, 10 V,+/- 20%, X5R, 0402", Cap_Case=0402, Manufacturer="Wurth Elektronik", Supplier Part Number 1=732-7489-1-ND, TempCo=X5R, Tolerance_%=20%, Value1=Unknown, Value2=10V, ValueDisplayed=1uF
C30 C32: library part CMP-0006639-2, "CAP, CERM, 0.01 uF, 16 V, +/- 10%, X7R, 0402", Cap_Case=0402, Manufacturer=MuRata, Supplier Part Number 1=490-1313-1-ND, TempCo=X7R, Tolerance_%=10%, Value1=Unknown, Value2=16V, ValueDisplayed=0.01uF
C31: library part CMP-0006594-2, "CAP, CERM, 2.2 uF, 16 V, +/- 10%, X5R, 0402", Cap_Case=0402, Manufacturer=MuRata, PartNumber=GRM155R61C225KE11D, Supplier Part Number 1=490-10695-1-ND, TempCo=X5R, Tolerance_%=10%, Value1=Unknown, Value2=16V
C34: library part CMP-0084376-1, "CAP, Tantalum Polymer, 10 µF, 10 V,+/- 20%, 0.08 ohm, 3216-18 SMD", Cap_Case=3216-18, Manufacturer=Kemet, Tolerance_%=20%, Value1="0.08 ohm", Value2=10V, ValueDisplayed=10µF
C38 C39 C40 C41 C42 C43 C46: library part CMP-0007081-4, "CAP, CERM, 1000 pF, 100 V, +/- 10%, X7R, AEC-Q200 Grade 1, 0603", Cap_Case=0603, Manufacturer=TDK, Supplier Part Number 1=445-5806-1-ND, TempCo=X7R, Tolerance_%=10%, Value1="1.97137 ohm", Value2=100V, ValueDisplayed=1000pF
C47 C48 C49 C50: library part CMP-0064916-2, "CAP, CERM, 10 pF, 50 V,+/- 1%, C0G/NP0, 0402", Cap_Case=0402, Manufacturer=MuRata, Supplier Part Number 1=490-6186-1-ND, TempCo=C0G/NP0, Tolerance_%=1%, Value1=Unknown, Value2=50V, ValueDisplayed=10pF
C51: library part CMP-0007836-1, "CAP, CERM, 2.2 uF, 50 V, +/- 10%, X5R, 0805", Cap_Case=0805, Manufacturer=TDK, Supplier Part Number 1=445-5976-1-ND, TempCo=X5R, Tolerance_%=10%, Value1="0.00366 ohm", Value2=50V, ValueDisplayed=2.2uF
D1 D3 D7: library part CMP-1426-00009-1, "SMD mono-color Chip LED, WL-SMCW, Bright Green", Color="Bright Green", Manufacturer="Wuerth Elektronik"
D2: library part CMP-1426-00010-1, "SMD mono-color Chip LED, WL-SMCW, Super Red", Color="Super Red", Manufacturer="Wuerth Elektronik"
D4: library part CMP-08607-000009-1, "TVS DIODE 36V 58.1V DO214AC", Breakdown Voltage=40V, Clamping Voltage=58.1V, Manufacturer="Littelfuse Inc", Max Junction Temp=+150°C, Package=SMAJ-CA, Peak Pulse Current=6.9A, Peak Pulse Power=400W, Reverse Standoff Voltage=36V, Temperature="-65°C to +150°C", Temperature Range Low=-65°C
D5: library part CMP-0002947-3, "LED, Red, SMD", Color=Red, Manufacturer="Wurth Elektronik", Power_TotalModule=72mW, Value1=0.072W, Value2=2V
D6: "LED, Green, SMD", Color=green, Manufacturer="Wurth Elektronik", PartNumber=150060VS75000, Value1=W, Value2=2V
D8: library part CMP-0028882-1, "Diode, Schottky, 40 V, 0.75 A, AEC-Q101, SOD-323", Manufacturer="Infineon Technologies", Supplier Part Number 1=BAT165E6327HTSA1CT-ND, Value1=0.75A, Value2=0.74V
F1 F2: library part CMP-0077200-3, "Fuse, 30 A, 250 VAC, 100 VDC, SMD", Irating_A=30A, Manufacturer=Littelfuse, Supplier Part Number 1=F6439CT-ND
FID1 FID2 FID3: library part CMP-0077181-1, "Fiducial mark.  There is nothing to buy or mount.", Manufacturer=N/A
H1 H2 H3 H4: library part CMP-0003620-1, "Bumpon, Hemisphere, 0.44 X 0.20, Clear", Manufacturer=3M, Supplier Part Number 1=SJ5303-7-ND
J1: library part CMP-77940-000002-1, "CONN HEADER VERT 3POS 2.54MM", Current Rating=3A, Manufacturer="Metz Connect", Temperature="-40°C to +105°C", Temperature Range High=+105°C, Temperature Range Low=-40°C
J2: library part CMP-0075595-1, "Header, 2.54mm, 8x2, Gold, SMT", Color=Black, Current_A=4.9A, Manufacturer=Samtec, Supplier Part Number 1=SAM8884-ND, Voltage_V=475V
J3 J8 J9: library part CMP-0055418-2, "Banana Jack Insul Nylon Red, R/A, TH", Color=Red, Current_A=25A, Manufacturer="Cal Test Electronics", Supplier Part Number 1=BKCT3151SP-2-ND, Voltage_V=1kV
J4: library part CMP-0054586-1, "Header, 2.54 mm, 12x1, Gold, TH", Color=Black, Current_A=3A, Manufacturer="Sullins Connector Solutions", Supplier Part Number 1=S1021E-12-ND, Voltage_V=1.8kV
J5: library part CMP-0086014-1, "Header, 2.54mm, 7x2, Gold, TH", Color=Black, Current_A=3A, Manufacturer="Wurth Elektronik", Voltage_V=250V
J6: "Receptacle, USB 2.0, Micro B, 5 Position, R/A, SMT", Color=Black, Current_A=1.8A, Manufacturer=Molex, PartNumber=1051640001, Supplier Part Number 1=WM11263CT-ND, Voltage_V=30V
J7: library part CMP-0002339-2, "Header, 100mil, 7x2, Tin, TH", Color=Black, Current_A=3A, Manufacturer="Sullins Connector Solutions", Supplier Part Number 1=S2012E-07-ND, Voltage_V=1.8kV
J10 J11 J12: library part CMP-0055598-2, "Header, 2.54mm, 5x2, Gold, SMT", Color=Black, Current_A=5.4A, Manufacturer=Samtec, Supplier Part Number 1=SAM8741-ND, Voltage_V=475V
J13: library part CMP-0079534-2, "Header, 2.54mm, 3x2, Gold, SMT", Color=Black, Current_A=3A, Manufacturer="Wurth Elektronik", Supplier Part Number 1=732-5461-5-ND, Voltage_V=250V
J14: library part CMP-0086764-1, Current_A=57A, Manufacturer=Wurth, Voltage_V=750V
J15: library part CMP-0075110-1, "1mm Uninsulated Shorting Plug, 10.16mm spacing, TH", Manufacturer=Harwin, Supplier Part Number 1=952-1873-ND
J17: library part CMP-0055417-1, "Banana Jack Insul Nylon Black, R/A, TH", Color=Black, Current_A=25A, Manufacturer="Cal Test Electronics", Supplier Part Number 1=BKCT3151SP-0-ND, Voltage_V=1kV
L1: library part CMP-0226-00123-1, "SMD High Current Cube Inductor WE-HCC, L=1.00 µH", Inductance="1.00 µH"
L2 L3: library part CMP-0081962-1, "Ferrite Bead, 150 ohm @ 100 MHz, 0.7 A, 0603", Manufacturer=MuRata, Supplier Part Number 1=490-14035-1-ND, Value1="0.35 ohm", Value2=0.7A, ValueDisplayed="150 ohm"
LBL1: library part CMP-0003625-1, "Thermal Transfer Printable Labels, 0.650\" W x 0.200\" H - 10,000 per roll", Manufacturer=Brady, Supplier Part Number 1=97C5133
Logo1: library part CMP-0074844-1
Logo2: library part CMP-0074838-1, "Texas Instrument Corporate Signature"
Logo3: library part CMP-0074847-1, "FCC_disclaimer"
Logo4: library part CMP-0074769-1
Logo5: library part CMP-0074836-1, "IEC 61010-1 Caution Warning"
LOGO6: library part CMP-0074837-1, "IEC 61010-1 Hot Surface Warning"
Q1: library part CMP-0000714-1, "MOSFET, N-CH, 40 V, 100 A, DQJ0008A (VSONP-8)", Alternate Manufacturer=None, Manufacturer="Texas Instruments", Supplier Part Number 1=296-45231-1-ND, Value1=0.004, Value2="47 nC"
R1 R68: library part CMP-0025886-3, "RES, 10 k, 5%, 0.1 W, 0603", Manufacturer="Yageo America", Power_W=100mW, Supplier Part Number 1=311-10KGRCT-ND, TempCo="100 ppm/C", Tolerance_%=5%, Value2=0.1W, Value_Code=10k0, ValueDisplayed=10k
R2 R3 R20: "RES, 330, 5%, 0.1 W, AEC-Q200 Grade 0, 0603", Manufacturer=Vishay-Dale, PartNumber=CRCW0603330RJNEA, Power_W=100mW, Supplier Part Number 1=541-330GCT-ND, TempCo="200 ppm/C", Tolerance_%=5%, Value2=0.1W, Value_Code=330R, ValueDisplayed=330
R4: library part CMP-0082533-1, "RES, 4.99 k, 1%, 0.1 W, 0603", Manufacturer=Vishay-Dale, Power_W=100mW, Supplier Part Number 1=541-3985-1-ND, TempCo="100 ppm/C", Tolerance_%=1%, Value2=0.1W, Value_Code=4k99, ValueDisplayed=4.99k
R5: library part CMP-0023129-5, "RES, 470, 1%, 0.1 W, 0603", Manufacturer=Yageo, Power_W=100mW, Supplier Part Number 1=311-470HRCT-ND, TempCo="100 ppm/C", Tolerance_%=1%, Value2=0.1W, Value_Code=470R, ValueDisplayed=470
R6: library part CMP-0023235-5, "RES, 680, 1%, 0.1 W, 0603", Manufacturer=Yageo, Power_W=100mW, Supplier Part Number 1=311-680HRCT-ND, TempCo="100 ppm/C", Tolerance_%=1%, Value2=0.1W, Value_Code=680R, ValueDisplayed=680
R7: library part CMP-0022895-5, "RES, 1.00 k, 1%, 0.1 W, 0603", Manufacturer=Yageo, Power_W=100mW, Supplier Part Number 1=311-1.00KHRCT-ND, TempCo="100 ppm/C", Tolerance_%=1%, Value2=0.1W, Value_Code=1k00, ValueDisplayed=1.00k
R8: library part CMP-0022883-5, "RES, 1.50 k, 1%, 0.1 W, 0603", Manufacturer=Yageo, Power_W=100mW, Supplier Part Number 1=311-1.50KHRCT-ND, TempCo="100 ppm/C", Tolerance_%=1%, Value2=0.1W, Value_Code=1k50, ValueDisplayed=1.50k
R9: library part CMP-0022986-5, "RES, 2.20 k, 1%, 0.1 W, 0603", Manufacturer=Yageo, Power_W=100mW, Supplier Part Number 1=311-2.20KHRCT-ND, TempCo="100 ppm/C", Tolerance_%=1%, Value2=0.1W, Value_Code=2k20, ValueDisplayed=2.20k
R10: library part CMP-0023081-5, "RES, 3.30 k, 1%, 0.1 W, 0603", Manufacturer=Yageo, Power_W=100mW, Supplier Part Number 1=311-3.30KHRCT-ND, TempCo="100 ppm/C", Tolerance_%=1%, Value2=0.1W, Value_Code=3k30, ValueDisplayed=3.30k
R11: library part CMP-0023153-5, "RES, 4.70 k, 1%, 0.1 W, 0603", Manufacturer=Yageo, Power_W=100mW, Supplier Part Number 1=311-4.70KHRCT-ND, TempCo="100 ppm/C", Tolerance_%=1%, Value2=0.1W, Value_Code=4k70, ValueDisplayed=4.70k
R12: library part CMP-0023253-5, "RES, 6.80 k, 1%, 0.1 W, 0603", Manufacturer=Yageo, Power_W=100mW, Supplier Part Number 1=311-6.80KHRCT-ND, TempCo="100 ppm/C", Tolerance_%=1%, Value2=0.1W, Value_Code=6k80, ValueDisplayed=6.80k
R13 R14 R15 R16 R17 R39 R40 R52: library part CMP-0086358-1, "RES, 0, 0%, 0.25 W, AEC-Q200 Grade 0, 0603", Manufacturer=Rohm, Power_W=250mW, Tolerance_%=0%, Value2=0.25W, Value_Code=0000, ValueDisplayed=0
R18: library part CMP-0025925-5, "RES, 47 k, 5%, 0.1 W, 0603", Manufacturer=Yageo, Power_W=100mW, Supplier Part Number 1=311-47KGRCT-ND, TempCo="100 ppm/C", Tolerance_%=5%, Value2=0.1W, Value_Code=47k0, ValueDisplayed=47k
R19 R22 R23 R24 R25 R26 R27 R28 R29 R30 R31: library part CMP-2000-03817-1, Manufacturer="Vishay Dale"
R21 R67 R69 R70 R71 R72: library part CMP-0025886-5, "RES, 10 k, 5%, 0.1 W, 0603", Manufacturer=Yageo, Power_W=100mW, Supplier Part Number 1=311-10KGRCT-ND, TempCo="100 ppm/C", Tolerance_%=5%, Value2=0.1W, Value_Code=10k0, ValueDisplayed=10k
R32: library part CMP-0026190-2, "RES, 240 k, 1%, 0.063 W, AEC-Q200 Grade 0, 0402", Manufacturer=Vishay-Dale, Power_W=63mW, Supplier Part Number 1=541-240KLCT-ND, TempCo="100 ppm/C", Tolerance_%=1%, Value2=0.063W, Value_Code=240k
R33: library part CMP-0026934-3, "RES, 470, 5%, 0.063 W, AEC-Q200 Grade 0, 0402", Manufacturer=Vishay-Dale, Power_W=63mW, Supplier Part Number 1=541-470JCT-ND, TempCo="200 ppm/C", Tolerance_%=5%, Value2=0.063W, Value_Code=470R, ValueDisplayed=470
R34: library part CMP-0026914-3, "RES, 390, 5%, 0.063 W, AEC-Q200 Grade 0, 0402", Manufacturer=Vishay-Dale, Power_W=63mW, Supplier Part Number 1=541-390JCT-ND, TempCo="200 ppm/C", Tolerance_%=5%, Value2=0.063W, Value_Code=390R, ValueDisplayed=390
